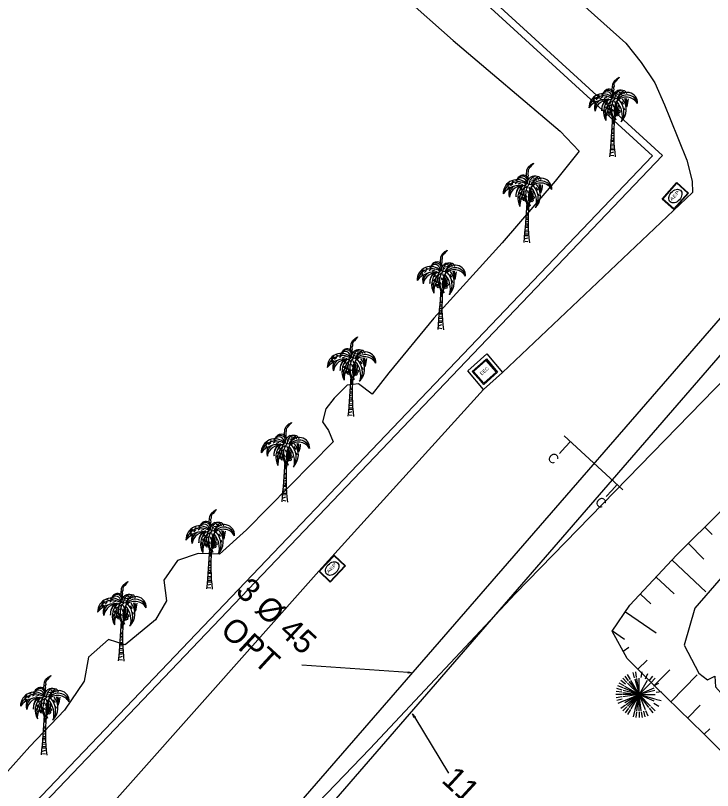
# Model space of a CAD drawing. Extents: x 343997 to 344255, y 298512 to 298767.
# Drawn here: x 344122.55 to 344152.54, y 298638.19 to 298671.53 of the extents above; entities that cross this region are included whole.
import ezdxf

# ---------------------------------------------------------------- set-up
doc = ezdxf.new("R2010")
doc.units = 0
for name, color, linetype in [('Default', 7, 'Continuous'), ('DH_CADRE-CARTOUCHE', 7, 'Continuous'), ('DIR-Projet VRD1', 7, 'Continuous'), ('EDE - coupe BT', 7, 'Continuous'), ('GO_DALLE', 7, 'Continuous'), ('O-Projet New VRD', 7, 'Continuous'), ('OPT texte', 7, 'Continuous'), ('OPT VRD', 7, 'Continuous'), ('PC_REBAR', 7, 'Continuous'), ('PS_OBJECT', 7, 'Continuous'), ('RES_EAU', 7, 'Continuous'), ('RES_ELECTRICITE', 7, 'Continuous')]:
    doc.layers.add(name, color=color, linetype=linetype)

# ---------------------------------------------------------------- blocks, each defined once
blk = doc.blocks.new('RES_EAU')
at = {"layer": 'RES_EAU'}
for points in [[(0, 0), (0, 0.1), (0.1, 0.1), (0.1, 0)], [(0.0025, 0.0025), (0.0025, 0.0975), (0.0975, 0.0975), (0.0975, 0.0025)]]:
    blk.add_lwpolyline(points, close=True, dxfattribs=at)
blk.add_circle((0.05, 0.05), 0.035, dxfattribs=at)
blk.add_text('AEP', height=0.02, dxfattribs=at).set_placement((0.0224, 0.0448))
blk = doc.blocks.new('RES_ELECTRICITE')
at = {"layer": 'RES_ELECTRICITE'}
for points in [[(0, 0), (0, 0.1), (0.1, 0.1), (0.1, 0)], [(0.005, 0.005), (0.005, 0.095), (0.095, 0.095), (0.095, 0.005)]]:
    blk.add_lwpolyline(points, close=True, dxfattribs=at)
blk.add_text('EEC', height=0.02, dxfattribs=at).set_placement((0.0237, 0.046))
blk = doc.blocks.new('COCO')
at = {"layer": 'Default'}
for p, q in [((-0.0037, 0.106), (0.0056, 0.1071)), ((0.0058, 0.114), (-0.003, 0.1162)), ((-0.0026, 0.1226), (0.0061, 0.1212)), ((-0.0046, 0.0891), (0.0052, 0.0927)), ((0.0054, 0.0998), (-0.0041, 0.0985)), ((-0.0068, 0.0371), (0.0045, 0.0374)), ((0.0045, 0.047), (-0.0065, 0.0453)), ((-0.0062, 0.0537), (0.0046, 0.0552)), ((0.0047, 0.0655), (-0.0058, 0.0642)), ((0.0046, 0.0033), (-0.0076, 0.0051)), ((-0.0073, 0.017), (0.0045, 0.0209)), ((0.0045, 0.0292), (-0.007, 0.0288))]:
    blk.add_line(p, q, dxfattribs=at)
for points in [[(0.0029, 0.2551), (-0.0016, 0.2896), (0.0002, 0.3125), (0.0059, 0.3241), (0.0173, 0.3348), (0.0189, 0.3356), (0.0282, 0.3415), (0.0266, 0.3373), (0.02, 0.3318), (0.0143, 0.3247), (0.0093, 0.32), (0.0081, 0.3165), (0.0057, 0.3133), (0.0057, 0.3099), (0.006, 0.3037), (0.0039, 0.2989), (0.0039, 0.2944), (0.0049, 0.2877), (0.0037, 0.2841), (0.0013, 0.2736)], [(-0.0487, 0.268), (-0.0386, 0.265)], [(0.0013, 0.2736), (0.0036, 0.2813), (0.0046, 0.2746)], [(0.0196, 0.2687), (0.0323, 0.2715)], [(0.0283, 0.2765), (0.0331, 0.2786)], [(-0.0746, 0.2559), (-0.0864, 0.2483)], [(-0.077, 0.2413), (-0.0836, 0.2333)], [(-0.0607, 0.2534), (-0.0704, 0.2443)], [(-0.0636, 0.2639), (-0.0541, 0.2608)], [(-0.0421, 0.258), (-0.0503, 0.2523)], [(-0.0183, 0.2493), (-0.0348, 0.2417), (-0.0401, 0.2307), (-0.0448, 0.2203), (-0.0471, 0.2086), (-0.0474, 0.2023), (-0.0466, 0.1973), (-0.0455, 0.2054), (-0.0451, 0.2146), (-0.0387, 0.2292), (-0.0351, 0.2354), (-0.0284, 0.2404), (-0.0233, 0.2445), (-0.0012, 0.2495)], [(-0.0256, 0.2553), (-0.0385, 0.2508)], [(0.0015, 0.2414), (-0.0056, 0.2352)], [(0.0081, 0.2404), (0.0106, 0.2299)], [(0.0133, 0.2608), (0.0185, 0.2634)], [(0.0385, 0.237), (0.0469, 0.2254)], [(-0.0276, 0.2151), (-0.0329, 0.2086)], [(-0.0203, 0.2314), (-0.0274, 0.2258)], [(-0.023, 0.2152), (-0.0237, 0.2043)], [(-0.0161, 0.2218), (-0.0158, 0.2122)], [(-0.0059, 0.2024), (-0.0083, 0.1998)], [(-0.004, 0.2247), (-0.0081, 0.2179)], [(-0.0025, 0.2032), (0.0002, 0.1954)], [(0.0022, 0.224), (0.0043, 0.213)], [(0.0473, 0.2115), (0.0509, 0.2012)], [(-0.0321, 0.1997), (-0.0364, 0.19)], [(-0.0055, 0.0716), (0.0048, 0.0717), (0.0049, 0.0787), (-0.0051, 0.0795)]]:
    blk.add_lwpolyline(points, dxfattribs=at)
for centre, radius in [((-0.0144, 0.1978), 0.00616), ((0.0254, 0.1938), 0.00628), ((-0.0187, 0.1897), 0.00384), ((-0.0124, 0.1896), 0.00376), ((-0.011, 0.184), 0.00471), ((0.0134, 0.1862), 0.00549), ((0.0208, 0.1822), 0.00626)]:
    blk.add_circle(centre, radius, dxfattribs=at)
for centre, radius, start, end in [((-0.0427, 0.2113), 0.0595, 43.6121, 181.4625), ((-0.0123, 0.259), 0.0323, 122.3475, 158.7636), ((-0.0199, 0.2618), 0.0238, 4.5218, 154.101), ((-0.0252, 0.2556), 0.0231, 4.2441, 134.2103), ((-0.016, 0.2647), 0.0255, 21.0861, 122.3475), ((0.0376, 0.2508), 0.0372, 113.7681, 175.3309), ((0.0376, 0.2508), 0.0372, 113.7681, 175.3309), ((0.0418, 0.2527), 0.0326, 97.1248, 183.9512), ((0.1025, 0.2053), 0.0958, 126.6858, 153.1664), ((0.0618, 0.2316), 0.0451, 356.1627, 159.0009), ((0.0344, 0.2407), 0.0451, 69.0817, 104.862), ((-0.1005, 0.1577), 0.1786, 37.5668, 40.5156), ((-0.0254, 0.228), 0.0869, 28.4725, 37.0965), ((0.0493, 0.2767), 0.00679, 35.3205, 126.6858), ((-0.0054, 0.2379), 0.0738, 25.8194, 35.3205), ((-0.0291, 0.1543), 0.0918, 76.7389, 142.8025), ((-0.038, 0.1964), 0.0648, 57.9192, 166.6201), ((-0.03, 0.212), 0.0482, 151.1331, 199.5942), ((-0.0196, 0.1874), 0.0565, 78.514, 171.3504), ((-0.032, 0.2055), 0.0433, 119.0834, 188.7621), ((0.0362, 0.1922), 0.0754, 136.7113, 208.8221), ((0.0551, 0.179), 0.0879, 137.733, 194.3716), ((0.062, 0.2159), 0.0753, 153.0868, 230.1124), ((0.0659, 0.2068), 0.0718, 142.3554, 222.2794), ((-0.0007, 0.2465), 0.00563, 81.7475, 144.3035), ((-0.0189, 0.121), 0.1324, 71.3715, 81.7475), ((0.0294, 0.2595), 0.0256, 198.6765, 199.7627), ((0.0963, 0.1939), 0.09, 143.9866, 203.4288), ((0.059, 0.2015), 0.0548, 29.5654, 139.3517), ((-0.0543, 0.1744), 0.096, 344.8781, 41.1461), ((-0.0341, 0.19), 0.0828, 46.9767, 50.1231), ((0.0609, 0.2187), 0.0468, 12.1077, 148.3146), ((-0.0157, 0.2027), 0.074, 51.2475, 54.5217), ((-0.0341, 0.19), 0.0828, 334.0687, 41.194), ((-0.0157, 0.2027), 0.074, 315.1472, 39.0239), ((-0.1704, 0.1849), 0.2327, 7.5978, 16.3666), ((-0.0254, 0.228), 0.0869, 350.8883, 14.7063), ((-0.0482, 0.2552), 0.1161, 339.3597, 356.5925), ((0.0649, 0.1599), 0.0949, 145.5146, 182.4528), ((0.0544, 0.1816), 0.0474, 137.1953, 172.8987), ((0.0308, 0.2014), 0.0226, 121.4297, 182.29), ((2.7302, 0.0106), 2.7266, 175.4791, 176.5597), ((0.0311, 0.2152), 0.0219, 141.856, 191.5175), ((0.0372, 0.1847), 0.0277, 133.5956, 173.487), ((0.0808, 0.1542), 0.0777, 142.2358, 156.28), ((0.0242, 0.1964), 0.0147, 110.9727, 165.9756), ((0.0404, 0.1878), 0.0354, 125.0585, 146.3893), ((0.0398, 0.2098), 0.0301, 136.4569, 162.0685), ((0.0357, 0.2084), 0.0244, 133.1184, 172.7534), ((-0.0759, 0.1958), 0.0922, 344.8505, 15.8988), ((-0.0404, 0.2045), 0.0619, 329.4666, 26.6793), ((-0.0289, 0.211), 0.0564, 317.8279, 12.3386), ((-8.5428, 0.7294), 8.5622, 355.11326, 356.26352), ((-0.0279, 0.1637), 0.0281, 2.1499, 36.6325), ((0.0199, 0.166), 0.0176, 166.9443, 185.5966), ((-0.0265, 0.1505), 0.0316, 339.9997, 25.7228)]:
    blk.add_arc(centre, radius, start, end, dxfattribs=at)
blk.add_ellipse((2.7425, 0.0272), major_axis=(-2.7371, 0.0966), ratio=0.529859, start_param=6.255729, end_param=6.369141, dxfattribs=at)
blk = doc.blocks.new('ARB2')
at = {"layer": 'Default'}
for p, q in [((-0.0513, 0.0525), (-0.0688, 0.0702)), ((-0.0438, 0.0589), (-0.0588, 0.0786)), ((-0.0356, 0.0642), (-0.0481, 0.0858)), ((-0.0181, 0.0716), (-0.0244, 0.0956)), ((-0.0088, 0.0736), (-0.0119, 0.0983)), ((0.0106, 0.0736), (0.0144, 0.0983)), ((0.0287, 0.0684), (0.0388, 0.0914)), ((0.0456, 0.0589), (0.0612, 0.0786)), ((0.0531, 0.0525), (0.0706, 0.0702)), ((-0.0675, 0.0286), (-0.09, 0.0381)), ((-0.0631, 0.0373), (-0.0844, 0.0497)), ((-0.0575, 0.0453), (-0.0775, 0.0605)), ((0.065, 0.0373), (0.0862, 0.0497)), ((-0.0731, 0), (-0.0981, 0)), ((-0.0725, 0.01), (-0.0969, 0.0133)), ((-0.0706, 0.0195), (-0.0944, 0.0259)), ((0.0744, 0.01), (0.0987, 0.0133)), ((-0.0725, -0.01), (-0.0969, -0.0133)), ((-0.0706, -0.0195), (-0.0944, -0.0259)), ((-0.0675, -0.0287), (-0.09, -0.0383)), ((0.0725, -0.0195), (0.0963, -0.0259)), ((-0.0575, -0.0455), (-0.0775, -0.0605)), ((-0.0513, -0.0527), (-0.0688, -0.0702)), ((-0.0438, -0.0591), (-0.0588, -0.0787)), ((-0.0356, -0.0644), (-0.0481, -0.0859)), ((0.0456, -0.0591), (0.0612, -0.0787)), ((0.0531, -0.0527), (0.0706, -0.0702)), ((0.065, -0.0373), (0.0862, -0.0498)), ((-0.0181, -0.0717), (-0.0244, -0.0956)), ((-0.0088, -0.0737), (-0.0119, -0.0983)), ((0.0013, -0.0741), (0.0013, -0.0989)), ((0.0106, -0.0737), (0.0144, -0.0983)), ((0.02, -0.0717), (0.0263, -0.0956)), ((0.0287, -0.0686), (0.0388, -0.0916))]:
    blk.add_line(p, q, dxfattribs=at)
for points in [[(-0.0169, 0.0677), (0.0013, 0), (-0.06, 0.035)], [(0.0013, 0.0008), (0.0013, 0), (-0.0081, 0.0695)], [(0.0362, 0.0608), (0.0013, 0), (0.0013, 0.0702)], [(-0.0688, 0.0091), (0.0013, 0), (-0.0338, 0.0608)], [(-0.0487, 0.0495), (0.0013, 0), (-0.0669, 0.0181)], [(-0.0419, 0.0556), (0.0013, 0), (-0.0638, 0.0269)], [(0.0656, 0.0269), (0.0013, 0), (0.0506, 0.0495)], [(-0.0487, -0.0497), (0.0013, 0), (-0.0694, 0)], [(-0.0638, -0.0269), (0.0013, 0), (-0.0688, -0.0092)], [(-0.0169, -0.0678), (0.0013, 0), (-0.06, -0.0352)], [(-0.0544, -0.0428), (0.0013, 0), (-0.0338, -0.0608)], [(-0.0081, -0.0695), (0.0013, 0), (-0.0419, -0.0558)], [(0.0013, -0.0702), (0.0013, 0), (0, 0)], [(0.0688, 0.0181), (0.0013, 0), (0.0713, 0)], [(0.0438, -0.0558), (0.0013, 0), (0.0656, -0.0269)], [(0.0506, -0.0497), (0.0013, 0), (0.0688, -0.0181)], [(0.01, -0.0695), (0.0013, 0), (0.0281, -0.0648)], [(0.0019, 0), (0.0013, 0), (0.0013, -0.0009)]]:
    blk.add_lwpolyline(points, dxfattribs=at)

msp = doc.modelspace()

# ---------------------------------------------------------------- linework, layer by layer
at = {"layer": 'DH_CADRE-CARTOUCHE'}
for points in [[(344124.372, 298692.186), (344148.812, 298670.333), (344149.478, 298669.504), (344150.054, 298668.628), (344150.475, 298667.688), (344150.721, 298667.085), (344151.432, 298665.306), (344151.673, 298664.395), (344151.676, 298663.909), (344143.5, 298656.169), (344142.683, 298655.44), (344135.602, 298647.623), (344124.992, 298635.682), (344123.722, 298634.656), (344121.833, 298633.77), (344119.792, 298633.516), (344117.727, 298633.77), (344116.3, 298634.425), (344115.03, 298635.389), (344091.665, 298656.941), (344066.817, 298679.859)], [(344079.116, 298659.278), (344094.724, 298644.749), (344120.412, 298621.951), (344137.791, 298639.981), (344144.065, 298646.663), (344154.783, 298657.656), (344157.662, 298660.576), (344158.342, 298661.39), (344163.216, 298666.766), (344163.731, 298667.308), (344164.688, 298668.072), (344165.676, 298668.545), (344166.447, 298668.825), (344167.222, 298669.059), (344168.509, 298669.289), (344169.751, 298669.392), (344170.251, 298669.414), (344170.803, 298669.375), (344172.06, 298669.227), (344173.884, 298668.877), (344175.641, 298668.318)]]:
    msp.add_lwpolyline(points, dxfattribs=at)
msp.add_lwpolyline([(344143.292, 298656.184), (344142.699, 298655.656), (344142.223, 298656.23), (344142.816, 298656.759)], close=True, dxfattribs=at)
at = {"layer": 'DIR-Projet VRD1'}
msp.add_line((344161.215, 298666.549), (344127.144, 298627.25), dxfattribs=at)
at = {"layer": 'EDE - coupe BT'}
for p, q in [((344146.204, 298652.954), (344146.435, 298653.206)), ((344148.204, 298651.101), (344148.436, 298651.353))]:
    msp.add_line(p, q, dxfattribs=at)
for points in [[(344148.682, 298651.126), (344146.16, 298653.448)], [(344146.204, 298652.954), (344145.961, 298652.69)], [(344148.204, 298651.101), (344147.961, 298650.837)]]:
    msp.add_lwpolyline(points, dxfattribs=at)
at = {"layer": 'GO_DALLE'}
msp.add_lwpolyline([(344143.5, 298656.169), (344142.683, 298655.44), (344142.015, 298656.246), (344142.832, 298656.974)], close=True, dxfattribs=at)
at = {"layer": 'O-Projet New VRD'}
msp.add_lwpolyline([(344139.705, 298641.321), (344139.637, 298641.491), (344139.756, 298641.353)], close=True, dxfattribs=at)
msp.add_lwpolyline([(344139.731, 298641.337), (344141.189, 298638.937)], dxfattribs=at)
at = {"layer": 'OPT texte'}
msp.add_lwpolyline([(344139.453, 298643.27), (344134.875, 298643.584)], dxfattribs=at)
msp.add_lwpolyline([(344139.455, 298643.3), (344139.632, 298643.257), (344139.451, 298643.24)], close=True, dxfattribs=at)
at = {"layer": 'OPT VRD'}
msp.add_lwpolyline([(344154.293, 298660.137), (344127.646, 298629.457)], dxfattribs=at)
at = {"layer": 'PC_REBAR'}
msp.add_lwpolyline([(344129.915, 298683.811), (344149.954, 298665.484), (344120.649, 298634.816), (344119.758, 298634.843), (344094.693, 298657.614), (344119.626, 298684.533), (344119.467, 298684.803), (344094.267, 298657.595), (344119.638, 298634.546), (344120.774, 298634.512), (344150.383, 298665.499), (344130.117, 298684.033)], close=True, dxfattribs=at)
msp.add_lwpolyline([(344134.972, 298676.138), (344141.382, 298670.447), (344145.984, 298666.555), (344146.809, 298665.696), (344145.776, 298664.399), (344143.49, 298661.745), (344140.544, 298658.509), (344138.612, 298656.16), (344137.895, 298655.241), (344137.314, 298655.683), (344136.818, 298655.628), (344136.259, 298655.071), (344135.904, 298654.607), (344135.762, 298654.056), (344136.012, 298653.679), (344136.225, 298653.183), (344132.496, 298649.404), (344131.323, 298648.36), (344130.418, 298648.385), (344129.521, 298648.088), (344128.929, 298647.247), (344129.046, 298646.357), (344128.58, 298645.532), (344127.265, 298644.456), (344126.557, 298644.694), (344125.698, 298643.931), (344125.499, 298642.901), (344124.663, 298641.644), (344123.173, 298640.08), (344121.715, 298638.486)], dxfattribs=at)
at = {"layer": 'PS_OBJECT'}
for p, q in [((344152.217, 298649.524), (344152.532, 298649.208)), ((344151.508, 298648.818), (344152.174, 298648.15)), ((344150.807, 298648.105), (344152.258, 298646.744)), ((344150.122, 298647.375), (344150.888, 298646.657)), ((344149.438, 298646.645), (344149.887, 298646.225)), ((344148.796, 298645.882), (344150.122, 298644.981)), ((344148.234, 298645.055), (344148.748, 298644.705)), ((344148.703, 298644.181), (344148.936, 298644.356)), ((344149.331, 298643.413), (344149.724, 298643.806)), ((344150.037, 298642.705), (344150.7, 298643.386)), ((344150.754, 298642.007), (344151.887, 298643.171)), ((344151.47, 298641.31), (344152.009, 298641.862)), ((344152.187, 298640.611), (344152.42, 298640.844))]:
    msp.add_line(p, q, dxfattribs=at)
for points in [[(344162.586, 298631.249), (344158.463, 298634.677), (344155.322, 298637.466), (344152.157, 298640.641), (344150.03, 298642.712), (344148.876, 298643.869), (344148.225, 298645.042), (344148.989, 298646.167), (344150.999, 298648.31), (344152.976, 298650.281), (344154.876, 298652.174), (344156.31, 298653.84), (344157.421, 298655.01), (344158.446, 298655.921), (344159.147, 298656.242), (344160.098, 298656.281)], [(344160.098, 298656.281), (344158.45, 298653.962), (344154.227, 298648.857), (344151.775, 298646.036), (344151.324, 298644.439), (344151.952, 298643.242), (344152.321, 298642.95), (344152.643, 298643.115), (344152.674, 298642.658), (344154.315, 298640.791), (344156.42, 298638.569), (344157.669, 298637.128), (344162.586, 298631.249)]]:
    msp.add_lwpolyline(points, dxfattribs=at)

# ---------------------------------------------------------------- block references
at = {"layer": 'PC_REBAR', "xscale": 10, "yscale": 10}
for name, p in [('COCO', (344148.245, 298665.454)), ('COCO', (344144.555, 298661.759)), ('COCO', (344140.849, 298658.024)), ('COCO', (344136.988, 298654.287)), ('COCO', (344134.141, 298650.612)), ('COCO', (344130.907, 298646.866)), ('COCO', (344127.107, 298643.765)), ('COCO', (344123.79, 298639.722)), ('ARB2', (344149.366, 298642.319))]:
    msp.add_blockref(name, p, dxfattribs=at)
at = {"layer": 'RES_EAU'}
for p, xscale, yscale, rotation in [((344150.877, 298663.178), 9.543021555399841, 6.73516593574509, 48.34700999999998), ((344136.092, 298647.16), 9.6082128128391, 6.740226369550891, 46.645739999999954)]:
    msp.add_blockref('RES_EAU', p, dxfattribs=dict(at, xscale=xscale, yscale=yscale, rotation=rotation))
at = {"layer": 'RES_ELECTRICITE', "xscale": 7.94749276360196, "yscale": 7.461633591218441, "rotation": 41.72266169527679}
msp.add_blockref('RES_ELECTRICITE', (344142.699, 298655.656), dxfattribs=at)

# ---------------------------------------------------------------- texts
at = {"layer": 'EDE - coupe BT'}
for p in [(344145.4, 298652.465), (344147.452, 298650.563)]:
    msp.add_text('C', height=0.42, rotation=317.3672, dxfattribs=at).set_placement(p)
at = {"layer": 'O-Projet New VRD'}
msp.add_text('11 Ø 45', height=1.0003, rotation=317.3672, dxfattribs=at).set_placement((344140.838, 298638.586))
at = {"layer": 'OPT texte'}
for s, p in [('3 Ø 45', (344131.975, 298646.698)), ('OPT', (344131.313, 298645.019))]:
    msp.add_text(s, height=1.0003, rotation=317.3672, dxfattribs=at).set_placement(p)

doc.saveas('drawing.dxf')
